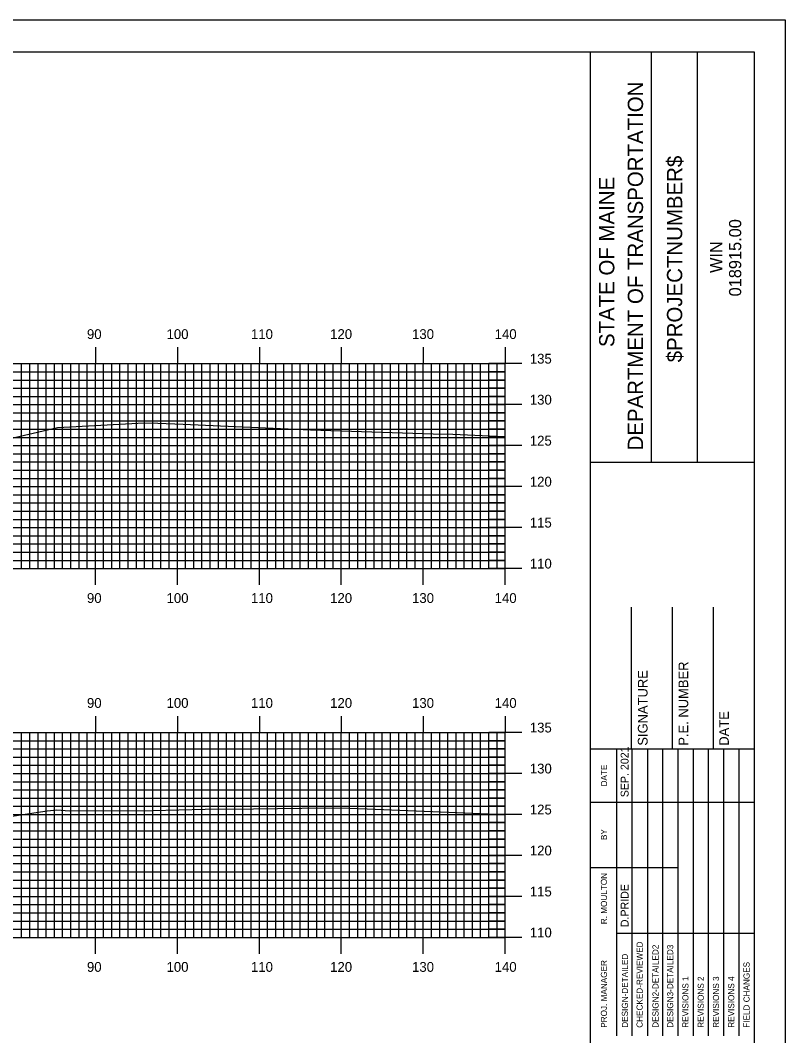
# Model space of a CAD drawing. Extents: x 842962 to 843305, y 363538 to 363758.
# Drawn here: x 843208.7 to 843302.1, y 363633.7 to 363757.6 of the extents above; entities that cross this region are included whole.
import ezdxf

# ---------------------------------------------------------------- set-up
doc = ezdxf.new("R2010")
doc.units = 0
for name, color, linetype in [('BORDER', 7, 'Continuous'), ('H_V ANNOTATION', 7, 'Continuous'), ('MAJOR', 7, 'Continuous'), ('MINOR', 7, 'Continuous'), ('PLOT BOUNDARY', 7, 'Continuous'), ('S_Roadway_Centerline', 7, 'Continuous')]:
    doc.layers.add(name, color=color, linetype=linetype)

msp = doc.modelspace()

# ---------------------------------------------------------------- linework, layer by layer
at = {"layer": 'BORDER'}
for p, q in [((843278.31, 363543.72), (843278.31, 363753.72)), ((843285.77, 363703.72), (843285.77, 363753.72)), ((843291.36, 363703.72), (843291.36, 363753.72)), ((843278.31, 363703.71), (843298.31, 363703.71)), ((843283.31, 363668.73), (843283.31, 363686.02)), ((843288.31, 363668.73), (843288.31, 363686.02)), ((843293.31, 363668.73), (843293.31, 363686.02)), ((843278.31, 363668.73), (843298.31, 363668.73))]:
    msp.add_line(p, q, dxfattribs=at)
msp.add_lwpolyline([(842978.31, 363543.72), (843298.31, 363543.72), (843298.31, 363753.72), (842978.31, 363753.72)], close=True, dxfattribs=at)
for points in [[(843281.54, 363662.23), (843281.54, 363668.73)], [(843283.41, 363633.73), (843283.41, 363668.73)], [(843285.27, 363668.73), (843285.27, 363633.73)], [(843287.13, 363633.73), (843287.13, 363668.73)], [(843289, 363633.73), (843289, 363668.73)], [(843290.86, 363633.73), (843290.86, 363668.73)], [(843292.72, 363633.73), (843292.72, 363668.73)], [(843294.59, 363633.73), (843294.59, 363668.73)], [(843296.45, 363633.73), (843296.45, 363668.73)], [(843281.54, 363633.73), (843281.54, 363667.31)], [(843278.31, 363662.23), (843298.31, 363662.23)], [(843278.31, 363654.23), (843281.54, 363654.23)], [(843281.54, 363654.23), (843288.99, 363654.23)], [(843281.54, 363646.23), (843298.31, 363646.23)]]:
    msp.add_lwpolyline(points, dxfattribs=at)
at = {"layer": 'MAJOR'}
for p, q in [((843217.91, 363717.73), (843217.91, 363715.72)), ((843227.91, 363717.73), (843227.91, 363715.72)), ((843237.91, 363717.73), (843237.91, 363715.72)), ((843247.91, 363717.73), (843247.91, 363715.72)), ((843257.91, 363717.73), (843257.91, 363715.72)), ((843267.91, 363717.73), (843267.91, 363715.72)), ((842987.91, 363715.72), (843267.91, 363715.72)), ((842987.91, 363715.72), (843267.91, 363715.72)), ((843217.91, 363690.72), (843217.91, 363715.72)), ((843227.91, 363690.72), (843227.91, 363715.72)), ((843237.91, 363690.72), (843237.91, 363715.72)), ((843247.91, 363690.72), (843247.91, 363715.72)), ((843257.91, 363690.72), (843257.91, 363715.72)), ((843269.92, 363715.72), (843265.91, 363715.72)), ((843267.91, 363690.72), (843267.91, 363715.72)), ((843267.91, 363690.72), (843267.91, 363715.72)), ((842987.91, 363710.72), (843267.91, 363710.72)), ((843269.92, 363710.72), (843265.91, 363710.72)), ((842987.91, 363705.72), (843267.91, 363705.72)), ((843269.92, 363705.72), (843265.91, 363705.72)), ((842987.91, 363700.72), (843267.91, 363700.72)), ((843269.92, 363700.72), (843265.91, 363700.72)), ((842987.91, 363695.72), (843267.91, 363695.72)), ((843269.92, 363695.72), (843265.91, 363695.72)), ((842987.91, 363690.72), (843267.91, 363690.72)), ((842987.91, 363690.72), (843267.91, 363690.72)), ((843217.91, 363688.72), (843217.91, 363690.72)), ((843227.91, 363688.72), (843227.91, 363690.72)), ((843237.91, 363688.72), (843237.91, 363690.72)), ((843247.91, 363688.72), (843247.91, 363690.72)), ((843257.91, 363688.72), (843257.91, 363690.72)), ((843269.92, 363690.72), (843265.91, 363690.72)), ((843267.91, 363688.72), (843267.91, 363690.72)), ((843217.91, 363672.73), (843217.91, 363670.72)), ((843227.91, 363672.73), (843227.91, 363670.72)), ((843237.91, 363672.73), (843237.91, 363670.72)), ((843247.91, 363672.73), (843247.91, 363670.72)), ((843257.91, 363672.73), (843257.91, 363670.72)), ((843267.91, 363672.73), (843267.91, 363670.72)), ((842987.91, 363670.72), (843267.91, 363670.72)), ((842987.91, 363670.72), (843267.91, 363670.72)), ((843217.91, 363645.72), (843217.91, 363670.72)), ((843227.91, 363645.72), (843227.91, 363670.72)), ((843237.91, 363645.72), (843237.91, 363670.72)), ((843247.91, 363645.72), (843247.91, 363670.72)), ((843257.91, 363645.72), (843257.91, 363670.72)), ((843269.92, 363670.72), (843265.91, 363670.72)), ((843267.91, 363645.72), (843267.91, 363670.72)), ((843267.91, 363645.72), (843267.91, 363670.72)), ((842987.91, 363665.72), (843267.91, 363665.72)), ((843269.92, 363665.72), (843265.91, 363665.72)), ((842987.91, 363660.72), (843267.91, 363660.72)), ((843269.92, 363660.72), (843265.91, 363660.72)), ((842987.91, 363655.72), (843267.91, 363655.72)), ((843269.92, 363655.72), (843265.91, 363655.72)), ((842987.91, 363650.72), (843267.91, 363650.72)), ((843269.92, 363650.72), (843265.91, 363650.72)), ((842987.91, 363645.72), (843267.91, 363645.72)), ((842987.91, 363645.72), (843267.91, 363645.72)), ((843217.91, 363643.72), (843217.91, 363645.72)), ((843227.91, 363643.72), (843227.91, 363645.72)), ((843237.91, 363643.72), (843237.91, 363645.72)), ((843247.91, 363643.72), (843247.91, 363645.72)), ((843257.91, 363643.72), (843257.91, 363645.72)), ((843269.92, 363645.72), (843265.91, 363645.72)), ((843267.91, 363643.72), (843267.91, 363645.72))]:
    msp.add_line(p, q, dxfattribs=at)
at = {"layer": 'MINOR'}
for p, q in [((843208.91, 363690.72), (843208.91, 363715.72)), ((843209.91, 363690.72), (843209.91, 363715.72)), ((843210.91, 363690.72), (843210.91, 363715.72)), ((843211.91, 363690.72), (843211.91, 363715.72)), ((843212.91, 363690.72), (843212.91, 363715.72)), ((843213.91, 363690.72), (843213.91, 363715.72)), ((843214.91, 363690.72), (843214.91, 363715.72)), ((843215.91, 363690.72), (843215.91, 363715.72)), ((843216.91, 363690.72), (843216.91, 363715.72)), ((843218.91, 363690.72), (843218.91, 363715.72)), ((843219.91, 363690.72), (843219.91, 363715.72)), ((843220.91, 363690.72), (843220.91, 363715.72)), ((843221.91, 363690.72), (843221.91, 363715.72)), ((843222.91, 363690.72), (843222.91, 363715.72)), ((843223.91, 363690.72), (843223.91, 363715.72)), ((843224.91, 363690.72), (843224.91, 363715.72)), ((843225.91, 363690.72), (843225.91, 363715.72)), ((843226.91, 363690.72), (843226.91, 363715.72)), ((843228.91, 363690.72), (843228.91, 363715.72)), ((843229.91, 363690.72), (843229.91, 363715.72)), ((843230.91, 363690.72), (843230.91, 363715.72)), ((843231.91, 363690.72), (843231.91, 363715.72)), ((843232.91, 363690.72), (843232.91, 363715.72)), ((843233.91, 363690.72), (843233.91, 363715.72)), ((843234.91, 363690.72), (843234.91, 363715.72)), ((843235.91, 363690.72), (843235.91, 363715.72)), ((843236.91, 363690.72), (843236.91, 363715.72)), ((843238.91, 363690.72), (843238.91, 363715.72)), ((843239.91, 363690.72), (843239.91, 363715.72)), ((843240.91, 363690.72), (843240.91, 363715.72)), ((843241.91, 363690.72), (843241.91, 363715.72)), ((843242.91, 363690.72), (843242.91, 363715.72)), ((843243.91, 363690.72), (843243.91, 363715.72)), ((843244.91, 363690.72), (843244.91, 363715.72)), ((843245.91, 363690.72), (843245.91, 363715.72)), ((843246.91, 363690.72), (843246.91, 363715.72)), ((843248.91, 363690.72), (843248.91, 363715.72)), ((843249.91, 363690.72), (843249.91, 363715.72)), ((843250.91, 363690.72), (843250.91, 363715.72)), ((843251.91, 363690.72), (843251.91, 363715.72)), ((843252.91, 363690.72), (843252.91, 363715.72)), ((843253.91, 363690.72), (843253.91, 363715.72)), ((843254.91, 363690.72), (843254.91, 363715.72)), ((843255.91, 363690.72), (843255.91, 363715.72)), ((843256.91, 363690.72), (843256.91, 363715.72)), ((843258.91, 363690.72), (843258.91, 363715.72)), ((843259.91, 363690.72), (843259.91, 363715.72)), ((843260.91, 363690.72), (843260.91, 363715.72)), ((843261.91, 363690.72), (843261.91, 363715.72)), ((843262.91, 363690.72), (843262.91, 363715.72)), ((843263.91, 363690.72), (843263.91, 363715.72)), ((843264.91, 363690.72), (843264.91, 363715.72)), ((843265.91, 363690.72), (843265.91, 363715.72)), ((843266.91, 363690.72), (843266.91, 363715.72)), ((842987.91, 363714.72), (843267.91, 363714.72)), ((843267.91, 363714.72), (843265.91, 363714.72)), ((842987.91, 363713.72), (843267.91, 363713.72)), ((843267.91, 363713.72), (843265.91, 363713.72)), ((842987.91, 363712.72), (843267.91, 363712.72)), ((842987.91, 363711.72), (843267.91, 363711.72)), ((843267.91, 363712.72), (843265.91, 363712.72)), ((843267.91, 363711.72), (843265.91, 363711.72)), ((842987.91, 363709.72), (843267.91, 363709.72)), ((843267.91, 363709.72), (843265.91, 363709.72)), ((842987.91, 363708.72), (843267.91, 363708.72)), ((843267.91, 363708.72), (843265.91, 363708.72)), ((842987.91, 363707.72), (843267.91, 363707.72)), ((842987.91, 363706.72), (843267.91, 363706.72)), ((843267.91, 363707.72), (843265.91, 363707.72)), ((843267.91, 363706.72), (843265.91, 363706.72)), ((842987.91, 363704.72), (843267.91, 363704.72)), ((843267.91, 363704.72), (843265.91, 363704.72)), ((842987.91, 363703.72), (843267.91, 363703.72)), ((843267.91, 363703.72), (843265.91, 363703.72)), ((842987.91, 363702.72), (843267.91, 363702.72)), ((843267.91, 363702.72), (843265.91, 363702.72)), ((842987.91, 363701.72), (843267.91, 363701.72)), ((843267.91, 363701.72), (843265.91, 363701.72)), ((842987.91, 363699.72), (843267.91, 363699.72)), ((843267.91, 363699.72), (843265.91, 363699.72)), ((842987.91, 363698.72), (843267.91, 363698.72)), ((843267.91, 363698.72), (843265.91, 363698.72)), ((842987.91, 363697.72), (843267.91, 363697.72)), ((843267.91, 363697.72), (843265.91, 363697.72)), ((842987.91, 363696.72), (843267.91, 363696.72)), ((843267.91, 363696.72), (843265.91, 363696.72)), ((842987.91, 363694.72), (843267.91, 363694.72)), ((843267.91, 363694.72), (843265.91, 363694.72)), ((842987.91, 363693.72), (843267.91, 363693.72)), ((843267.91, 363693.72), (843265.91, 363693.72)), ((842987.91, 363692.72), (843267.91, 363692.72)), ((843267.91, 363692.72), (843265.91, 363692.72)), ((842987.91, 363691.72), (843267.91, 363691.72)), ((843267.91, 363691.72), (843265.91, 363691.72)), ((842987.91, 363669.72), (843267.91, 363669.72)), ((843208.91, 363645.72), (843208.91, 363670.72)), ((843209.91, 363645.72), (843209.91, 363670.72)), ((843210.91, 363645.72), (843210.91, 363670.72)), ((843211.91, 363645.72), (843211.91, 363670.72)), ((843212.91, 363645.72), (843212.91, 363670.72)), ((843213.91, 363645.72), (843213.91, 363670.72)), ((843214.91, 363645.72), (843214.91, 363670.72)), ((843215.91, 363645.72), (843215.91, 363670.72)), ((843216.91, 363645.72), (843216.91, 363670.72)), ((843218.91, 363645.72), (843218.91, 363670.72)), ((843219.91, 363645.72), (843219.91, 363670.72)), ((843220.91, 363645.72), (843220.91, 363670.72)), ((843221.91, 363645.72), (843221.91, 363670.72)), ((843222.91, 363645.72), (843222.91, 363670.72)), ((843223.91, 363645.72), (843223.91, 363670.72)), ((843224.91, 363645.72), (843224.91, 363670.72)), ((843225.91, 363645.72), (843225.91, 363670.72)), ((843226.91, 363645.72), (843226.91, 363670.72)), ((843228.91, 363645.72), (843228.91, 363670.72)), ((843229.91, 363645.72), (843229.91, 363670.72)), ((843230.91, 363645.72), (843230.91, 363670.72)), ((843231.91, 363645.72), (843231.91, 363670.72)), ((843232.91, 363645.72), (843232.91, 363670.72)), ((843233.91, 363645.72), (843233.91, 363670.72)), ((843234.91, 363645.72), (843234.91, 363670.72)), ((843235.91, 363645.72), (843235.91, 363670.72)), ((843236.91, 363645.72), (843236.91, 363670.72)), ((843238.91, 363645.72), (843238.91, 363670.72)), ((843239.91, 363645.72), (843239.91, 363670.72)), ((843240.91, 363645.72), (843240.91, 363670.72)), ((843241.91, 363645.72), (843241.91, 363670.72)), ((843242.91, 363645.72), (843242.91, 363670.72)), ((843243.91, 363645.72), (843243.91, 363670.72)), ((843244.91, 363645.72), (843244.91, 363670.72)), ((843245.91, 363645.72), (843245.91, 363670.72)), ((843246.91, 363645.72), (843246.91, 363670.72)), ((843248.91, 363645.72), (843248.91, 363670.72)), ((843249.91, 363645.72), (843249.91, 363670.72)), ((843250.91, 363645.72), (843250.91, 363670.72)), ((843251.91, 363645.72), (843251.91, 363670.72)), ((843252.91, 363645.72), (843252.91, 363670.72)), ((843253.91, 363645.72), (843253.91, 363670.72)), ((843254.91, 363645.72), (843254.91, 363670.72)), ((843255.91, 363645.72), (843255.91, 363670.72)), ((843256.91, 363645.72), (843256.91, 363670.72)), ((843258.91, 363645.72), (843258.91, 363670.72)), ((843259.91, 363645.72), (843259.91, 363670.72)), ((843260.91, 363645.72), (843260.91, 363670.72)), ((843261.91, 363645.72), (843261.91, 363670.72)), ((843262.91, 363645.72), (843262.91, 363670.72)), ((843263.91, 363645.72), (843263.91, 363670.72)), ((843264.91, 363645.72), (843264.91, 363670.72)), ((843265.91, 363645.72), (843265.91, 363670.72)), ((843267.91, 363669.72), (843265.91, 363669.72)), ((843266.91, 363645.72), (843266.91, 363670.72)), ((842987.91, 363668.72), (843267.91, 363668.72)), ((843267.91, 363668.72), (843265.91, 363668.72)), ((842987.91, 363667.72), (843267.91, 363667.72)), ((843267.91, 363667.72), (843265.91, 363667.72)), ((842987.91, 363666.72), (843267.91, 363666.72)), ((843267.91, 363666.72), (843265.91, 363666.72)), ((842987.91, 363664.72), (843267.91, 363664.72)), ((843267.91, 363664.72), (843265.91, 363664.72)), ((842987.91, 363663.72), (843267.91, 363663.72)), ((843267.91, 363663.72), (843265.91, 363663.72)), ((842987.91, 363662.72), (843267.91, 363662.72)), ((843267.91, 363662.72), (843265.91, 363662.72)), ((842987.91, 363661.72), (843267.91, 363661.72)), ((843267.91, 363661.72), (843265.91, 363661.72)), ((842987.91, 363659.72), (843267.91, 363659.72)), ((843267.91, 363659.72), (843265.91, 363659.72)), ((842987.91, 363658.72), (843267.91, 363658.72)), ((843267.91, 363658.72), (843265.91, 363658.72)), ((842987.91, 363657.72), (843267.91, 363657.72)), ((843267.91, 363657.72), (843265.91, 363657.72)), ((842987.91, 363656.72), (843267.91, 363656.72)), ((843267.91, 363656.72), (843265.91, 363656.72)), ((842987.91, 363654.72), (843267.91, 363654.72)), ((843267.91, 363654.72), (843265.91, 363654.72)), ((842987.91, 363653.72), (843267.91, 363653.72)), ((843267.91, 363653.72), (843265.91, 363653.72)), ((842987.91, 363652.72), (843267.91, 363652.72)), ((843267.91, 363652.72), (843265.91, 363652.72)), ((842987.91, 363651.72), (843267.91, 363651.72)), ((843267.91, 363651.72), (843265.91, 363651.72)), ((842987.91, 363649.72), (843267.91, 363649.72)), ((843267.91, 363649.72), (843265.91, 363649.72)), ((842987.91, 363648.72), (843267.91, 363648.72)), ((843267.91, 363648.72), (843265.91, 363648.72)), ((842987.91, 363647.72), (843267.91, 363647.72)), ((843267.91, 363647.72), (843265.91, 363647.72)), ((842987.91, 363646.72), (843267.91, 363646.72)), ((843267.91, 363646.72), (843265.91, 363646.72))]:
    msp.add_line(p, q, dxfattribs=at)
at = {"layer": 'PLOT BOUNDARY'}
msp.add_lwpolyline([(842962.12, 363537.6), (843302.12, 363537.6), (843302.12, 363757.6), (842962.12, 363757.6)], close=True, dxfattribs=at)
at = {"layer": 'S_Roadway_Centerline'}
for points in [[(843203.28, 363705.59), (843213.27, 363707.92), (843223.86, 363708.49), (843225.52, 363708.47), (843228.63, 363708.35), (843244.14, 363707.63), (843259.12, 363707.16), (843261.51, 363707.1), (843267.77, 363706.82), (843267.91, 363706.82)], [(843200.45, 363659.4), (843212.04, 363661.17), (843213.2, 363661.28), (843214.74, 363661.18), (843224.89, 363661.21), (843231.32, 363661.38), (843237.2, 363661.39), (843246.03, 363661.52), (843248.91, 363661.47), (843251.06, 363661.39), (843262, 363660.94), (843267.91, 363660.7)]]:
    msp.add_lwpolyline(points, dxfattribs=at)

# ---------------------------------------------------------------- texts
at = {"layer": 'BORDER'}
for s, height, p in [('DEPARTMENT OF TRANSPORTATION', 1.8635, (843284.72, 363705.13)), ('$PROJECTNUMBER$', 1.8635, (843289.5, 363715.88)), ('STATE OF MAINE', 1.8635, (843281.22, 363717.74)), ('018915.00', 1.491, (843296.7, 363723.92)), ('WIN', 1.491, (843294.38, 363726.78)), ('SIGNATURE', 1.181, (843285.27, 363669.11)), ('P.E. NUMBER', 1.1811, (843290.23, 363669.11)), ('DATE', 1.181, (843295.19, 363669.11)), ('SEP. 2021', 0.969, (843282.96, 363662.82)), ('DATE', 0.743, (843280.32, 363664.14)), ('BY', 0.743, (843280.32, 363657.6)), ('R. MOULTON', 0.745, (843280.32, 363647.33)), ('D.PRIDE', 0.969, (843282.96, 363646.97)), ('CHECKED-REVIEWED', 0.7455, (843284.67, 363634.7)), ('DESIGN2-DETAILED2', 0.7455, (843286.61, 363634.7)), ('DESIGN3-DETAILED3', 0.7455, (843288.4, 363634.7)), ('DESIGN-DETAILED', 0.7455, (843282.88, 363634.7)), ('PROJ. MANAGER', 0.7455, (843280.32, 363634.7)), ('FIELD CHANGES', 0.7455, (843297.72, 363634.7)), ('REVISIONS 1', 0.7455, (843290.26, 363634.7)), ('REVISIONS 2', 0.7455, (843292.13, 363634.7)), ('REVISIONS 3', 0.7455, (843293.99, 363634.7)), ('REVISIONS 4', 0.7455, (843295.85, 363634.7))]:
    msp.add_text(s, height=height, rotation=90, dxfattribs=at).set_placement(p)
at = {"layer": 'H_V ANNOTATION'}
for s, p in [('90', (843216.88, 363718.72)), ('100', (843226.59, 363718.72)), ('110', (843236.89, 363718.72)), ('120', (843246.55, 363718.72)), ('130', (843256.54, 363718.72)), ('140', (843266.62, 363718.72)), ('135', (843270.91, 363715.72)), ('130', (843270.91, 363710.72)), ('125', (843270.91, 363705.72)), ('120', (843270.91, 363700.72)), ('115', (843270.91, 363695.72)), ('110', (843270.91, 363690.72)), ('90', (843216.88, 363686.52)), ('100', (843226.59, 363686.52)), ('110', (843236.89, 363686.52)), ('120', (843246.55, 363686.52)), ('130', (843256.54, 363686.52)), ('140', (843266.62, 363686.52)), ('90', (843216.88, 363673.72)), ('100', (843226.59, 363673.72)), ('110', (843236.89, 363673.72)), ('120', (843246.55, 363673.72)), ('130', (843256.54, 363673.72)), ('140', (843266.62, 363673.72)), ('135', (843270.91, 363670.72)), ('130', (843270.91, 363665.72)), ('125', (843270.91, 363660.72)), ('120', (843270.91, 363655.72)), ('115', (843270.91, 363650.72)), ('110', (843270.91, 363645.72)), ('90', (843216.88, 363641.52)), ('100', (843226.59, 363641.52)), ('110', (843236.89, 363641.52)), ('120', (843246.55, 363641.52)), ('130', (843256.54, 363641.52)), ('140', (843266.62, 363641.52))]:
    msp.add_text(s, height=1.2, dxfattribs=at).set_placement(p)

doc.saveas('drawing.dxf')
